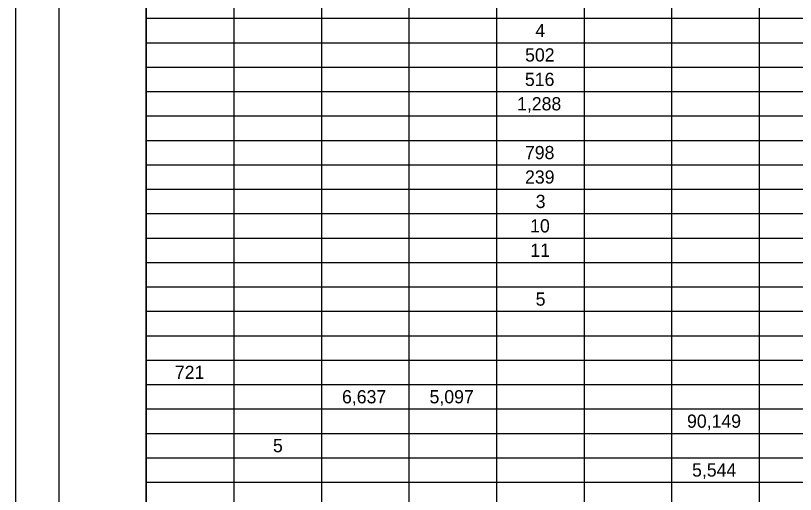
# Model space of a CAD drawing. Extents: x 0 to 34, y 0 to 22.
# Drawn here: x 0 to 8.95, y 11 to 16.49 of the extents above; entities that cross this region are included whole.
import ezdxf

# ---------------------------------------------------------------- set-up
doc = ezdxf.new("R2010")
doc.units = 0
for name, color, linetype in [('Default', 7, 'Continuous'), ('SH_Border', 7, 'Continuous'), ('SH_Cut_Line', 7, 'Continuous')]:
    doc.layers.add(name, color=color, linetype=linetype)

msp = doc.modelspace()

# ---------------------------------------------------------------- linework, layer by layer
at = {"layer": 'Default'}
for p, q in [((1.5, 21.5), (1.5, 0.5)), ((2.5046, 20.94), (2.5046, 0.5)), ((3.5092, 20.94), (3.5092, 0.5)), ((4.5138, 20.94), (4.5138, 0.5)), ((5.5184, 20.94), (5.5184, 0.5)), ((6.5229, 20.94), (6.5229, 0.5)), ((7.5275, 20.94), (7.5275, 0.5)), ((8.5321, 20.94), (8.5321, 0.5)), ((1.5, 16.46), (32, 16.46)), ((1.5, 16.18), (32, 16.18)), ((1.5, 15.9), (32, 15.9)), ((1.5, 15.62), (32, 15.62)), ((1.5, 15.34), (32, 15.34)), ((1.5, 15.06), (32, 15.06)), ((1.5, 14.78), (32, 14.78)), ((1.5, 14.5), (32, 14.5)), ((1.5, 14.22), (32, 14.22)), ((1.5, 13.94), (32, 13.94)), ((1.5, 13.66), (32, 13.66)), ((1.5, 13.38), (32, 13.38)), ((1.5, 13.1), (32, 13.1)), ((1.5, 12.82), (32, 12.82)), ((1.5, 12.54), (32, 12.54)), ((1.5, 12.26), (32, 12.26)), ((1.5, 11.98), (32, 11.98)), ((1.5, 11.7), (32, 11.7)), ((1.5, 11.42), (32, 11.42)), ((1.5, 11.14), (32, 11.14))]:
    msp.add_line(p, q, dxfattribs=at)
at = {"layer": 'SH_Border'}
for points in [[(0.5, 21.5), (1.5, 21.5), (1.5, 0.5), (0.5, 0.5)], [(1.5, 21.5), (33.5, 21.5), (33.5, 0.5), (1.5, 0.5)]]:
    msp.add_lwpolyline(points, close=True, dxfattribs=at)
at = {"layer": 'SH_Cut_Line'}
msp.add_lwpolyline([(0, 0), (34, 0), (34, 22), (0, 22)], close=True, dxfattribs=at)

# ---------------------------------------------------------------- texts
at = {"layer": 'Default'}
for s, height, p in [('4', 0.1515, (5.9636, 16.2442)), ('502', 0.15153, (5.8459, 15.9642)), ('516', 0.15153, (5.844, 15.6842)), ('1,288', 0.15153, (5.7539, 15.4042)), ('798', 0.15153, (5.8442, 14.8442)), ('239', 0.15153, (5.8453, 14.5642)), ('3', 0.1515, (5.9674, 14.2842)), ('10', 0.15153, (5.9039, 14.0042)), ('11', 0.15153, (5.9062, 13.7242)), ('5', 0.1515, (5.9672, 13.1642)), ('721', 0.15153, (1.8274, 12.3242)), ('6,637', 0.15153, (3.7453, 12.0442)), ('5,097', 0.15153, (4.7499, 12.0442)), ('90,149', 0.15153, (7.7038, 11.7642)), ('5', 0.1515, (2.9534, 11.4842)), ('5,544', 0.15153, (7.7616, 11.2042))]:
    msp.add_text(s, height=height, dxfattribs=at).set_placement(p)

doc.saveas('drawing.dxf')
